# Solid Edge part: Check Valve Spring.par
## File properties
Title: Check Valve Spring
Author: Dan
Template: Normal.par
Last saved by: Dan
Revision: 11
Application: Solid Edge
Density: 0 kg/mm^3
Accuracy: 0.99
Document Number: P52-020
Project Name: Piston Pump P52
Material: steel
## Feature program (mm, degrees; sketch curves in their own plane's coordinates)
helix protrusion "HelixProtrusion_1"  NumberOfTurns = 3.5; TaperEndRadius = 0.5 mm
helix protrusion "HelixProtrusion_2"  Pitch = 0.51 mm; NumberOfTurns = 1.5
helix protrusion "HelixProtrusion_3"  Pitch = 0.55 mm; NumberOfTurns = 1.5
sketch for "ExtrudedCutout_1" plane through (0, 0, 0) normal (0, -1, 0) x-axis (1, 0, 0)
extrude "ExtrudedCutout_1" cut finite 18 symmetric
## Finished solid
Body 1: solid body, 7 faces, 12 edges, 8 vertices.
  Faces by surface: plane 4, spline 3
  Edges by curve: circle 5, intersection 3, curve on surface 2, line 2
Bounding box of the edges (mm; curved faces can reach further): 11.800 x 7.124 x 7.046, from (-17.2003, -3.6, -3.5961) to (-5.4003, 3.5237, 3.4501).
Planar faces by outward normal: +x 1, +z 2, -x 1
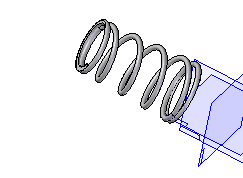
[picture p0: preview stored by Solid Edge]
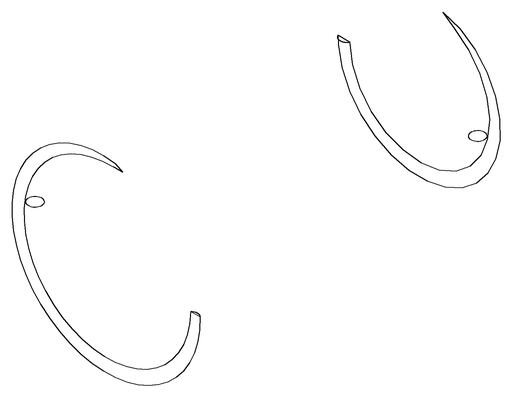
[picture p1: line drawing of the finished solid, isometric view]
